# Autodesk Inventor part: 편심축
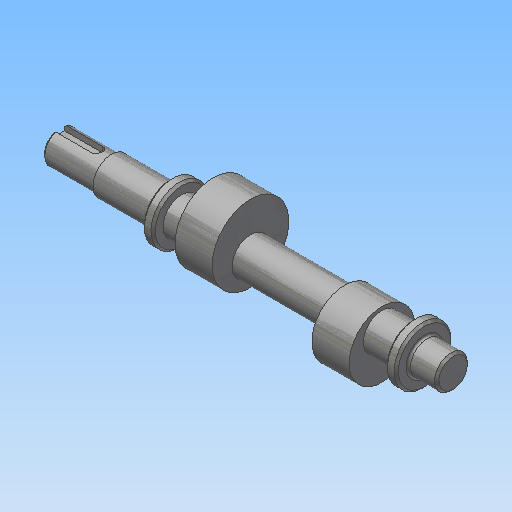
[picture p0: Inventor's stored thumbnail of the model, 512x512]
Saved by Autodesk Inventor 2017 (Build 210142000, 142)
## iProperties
Created: 2021-06
Part Number: 편심축
Material: 강철, 연강
Document SubType Name: Modeling
Designer: mdu-edu
Density: 7.86 g/cm^3
Appearance: 강철
Author: mdu-edu
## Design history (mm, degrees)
sketch "스케치1"
  geometry: L1 (0, 0)-(180, 0); L2 (180, 0)-(180, -7.5); L3 (180, -7.5)-(167, -7.5); L4 (167, -7.5)-(167, -13); L5 (167, -13)-(162, -13); L6 (162, -13)-(162, -8.5); L7 (162, -8.5)-(56, -8.5); L8 (56, -8.5)-(56, -13); L9 (56, -13)-(51, -13); L10 (51, -13)-(51, -8.5); L11 (51, -8.5)-(24, -8.5); L12 (24, -8.5)-(24, -7.5); L13 (24, -7.5)-(0, -7.5); L14 (0, -7.5)-(0, 0)
  constraints: 28 end point, 6 parallel, 3 horizontal, 3 vertical, 1 collinear, 1 perpendicular
  dimensions: "d0" = 15 diameter of L13 L1; "d2" = 26 diameter of L9 L1; "d3" = 26 diameter of L5 L1; "d4" = 15 diameter of L3 L1; "d5" = 17 diameter of L7 L1; "d6" = 17 diameter of L11 L1; "d7" = 24 distance between parallel lines of L12 L14; "d8" = 51 distance between parallel lines of L14 L10; "d10" = 5 distance of L8.end L9.end; "d11" = 5 distance of L4.end L5.end; "d12" = 13 distance between parallel lines of L4 L2; "d13" = 180 distance between parallel lines of L14 L2
revolve "회전1" sketch "스케치1" stored, may be unused: angle "d14" = 90 deg
node "작업 평면1"
sketch "스케치2"
  geometry: C1 r 17.5 at (0, 5); 1 further point
  constraints: 1 centre point, 1 vertical alignment
  dimensions: "d16" = 35 diameter of C1; "d17" = 5 distance of C1.centre point (0, 0)
extrude "돌출1" join sketch "스케치2" distance "d18" = 17; taper "d19" = 0 deg
node "작업 평면2"
sketch "스케치3"
  geometry: C1 r 15 at (0, -5); 1 further point
  constraints: 1 centre point, 1 vertical alignment
  dimensions: "d21" = 30 diameter of C1; "d22" = 5 distance of point (0, 0) C1.centre
extrude "돌출2" join sketch "스케치3" distance "d23" = 17; taper "d24" = 0 deg
chamfer "모따기1" distance "d29" = 1; stored, may be unused: second distance "d30" = 2, angle "d31" = 45 deg
node "작업 평면3"
sketch "스케치4"
  geometry: L1 (-5.5, 2.5)-(12, 2.5); L2 (12, 2.5)-(12, -2.5); L3 (12, -2.5)-(-5.5, -2.5); L4 (12, 6.5)-(12, -6.5) reference; A1 r 2.5 centre (-5.5, 0) between (-5.5, 2.5) and (-5.5, -2.5); 1 further point
  constraints: 6 end point, 2 point on circle, 2 tangent, 1 centre point, 1 collinear, 1 horizontal, 1 horizontal alignment, 1 midpoint, 1 parallel, 1 perpendicular
  dimensions: "d25" = 5 diameter of A1; "d32" = 20 dimension on A1 L4
extrude "돌출3" cut sketch "스케치4" distance "d27" = 3; taper "d28" = 0 deg
fillet "모깎기1" dims "d33" = 0.6
fillet "모깎기2" dims "d34" = 1
node "솔리드1"
other parameters: "d15" = -70.5, "d20" = -32.5
